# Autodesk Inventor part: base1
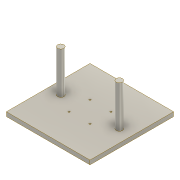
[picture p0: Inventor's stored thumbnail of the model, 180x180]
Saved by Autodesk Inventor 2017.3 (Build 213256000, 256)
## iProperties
Part Number: base1
Material: チタン
Document SubType Name: Modeling
Designer: kyushu-hep
Density: 4.51 g/cm^3
Appearance: チタン
Author: kyushu-hep
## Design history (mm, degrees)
sketch "スケッチ3"
  geometry: L1 (-100, 100)-(100, 100); L2 (100, 100)-(100, -100); L3 (100, -100)-(-100, -100); L4 (-100, -100)-(-100, 100); 1 further point
  constraints: 8 end point, 2 parallel, 1 horizontal, 1 perpendicular
  dimensions: "d19" = 100 distance from line of L1 point (0, 0); "d20" = 200 distance of L3.end L1.start; "d21" = 200 distance of L1.start L1.end; "d22" = 100 distance from line of L4 point (0, 0)
extrude "押し出し3" new body sketch "スケッチ3" distance "d23" = 10; taper "d24" = 0 deg
sketch "スケッチ4"
  geometry: C1 r 7.5 at (-70, 0); C2 r 7.5 at (70, 0); 1 further point
  constraints: 2 centre point
  dimensions: "d55" = 15 diameter of C1; "d57" = 15 diameter of C2; "d58" = 0 vertical distance of point (0, 0) C1.centre; "d59" = 70 distance of point (0, 0) C1.centre; "d62" = 0 vertical distance of point (0, 0) C2.centre; "d65" = 70 distance of C2.centre point (0, 0)
sketch "スケッチ6"
  geometry: L1 (52, -52)-(-52, -52); L2 (-52, -52)-(-52, 52); L3 (-52, 52)-(52, 52); L4 (52, 52)-(52, -52); L5 (52, -52)-(-52, 52); L6 (-52, -52)-(52, 52); C1 r 2 at (-25, 25); C2 r 2 at (25, 25); C3 r 2 at (-25, -25); C4 r 2 at (25, -25); 1 further point
  constraints: 12 end point, 4 centre point, 2 horizontal, 2 midpoint, 2 parallel, 1 perpendicular, 1 vertical, 6 other
  dimensions: "d38" = 4 diameter of C1; "d40" = 25 horizontal distance of point (0, 0) C1.centre; "d43" = 50 distance of C1.centre C2.centre; "d46" = 50 distance of C1.centre C3.centre; "d51" = 25 horizontal distance of point (0, 0) C2.centre
extrude "押し出し6" cut sketch "スケッチ6" distance "d49" = 10; taper "d50" = 0 deg
extrude "押し出し8" join sketch "スケッチ4" distance "d63" = 100; taper "d64" = 0 deg
node "ソリッド2"
